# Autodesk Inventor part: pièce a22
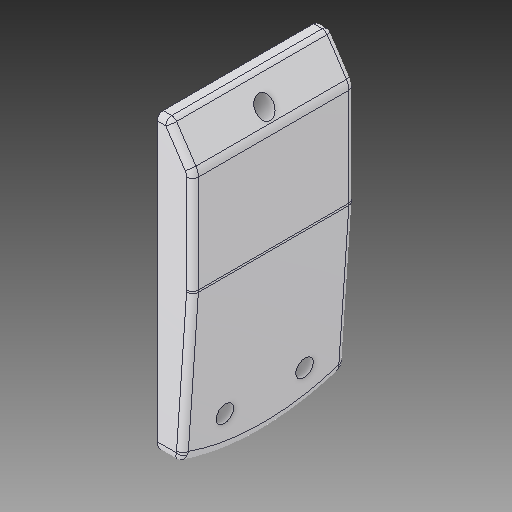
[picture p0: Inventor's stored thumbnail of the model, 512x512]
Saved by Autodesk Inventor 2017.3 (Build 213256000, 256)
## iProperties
Created: 2007-12
Part Number: pièce a22
Material: solidworks materials|Alliage 7079|22
Document SubType Name: Modeling
Designer: ficho
Density: 2.7 g/cm^3
Appearance: 227,227,233
Author: ficho
Sending System: SolidWorks 2009
Last Author: christophe
Last Saved: 2011-02-10
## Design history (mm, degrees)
extrude "Extrusion2"
node "Solide1"
